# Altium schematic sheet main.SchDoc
size A4
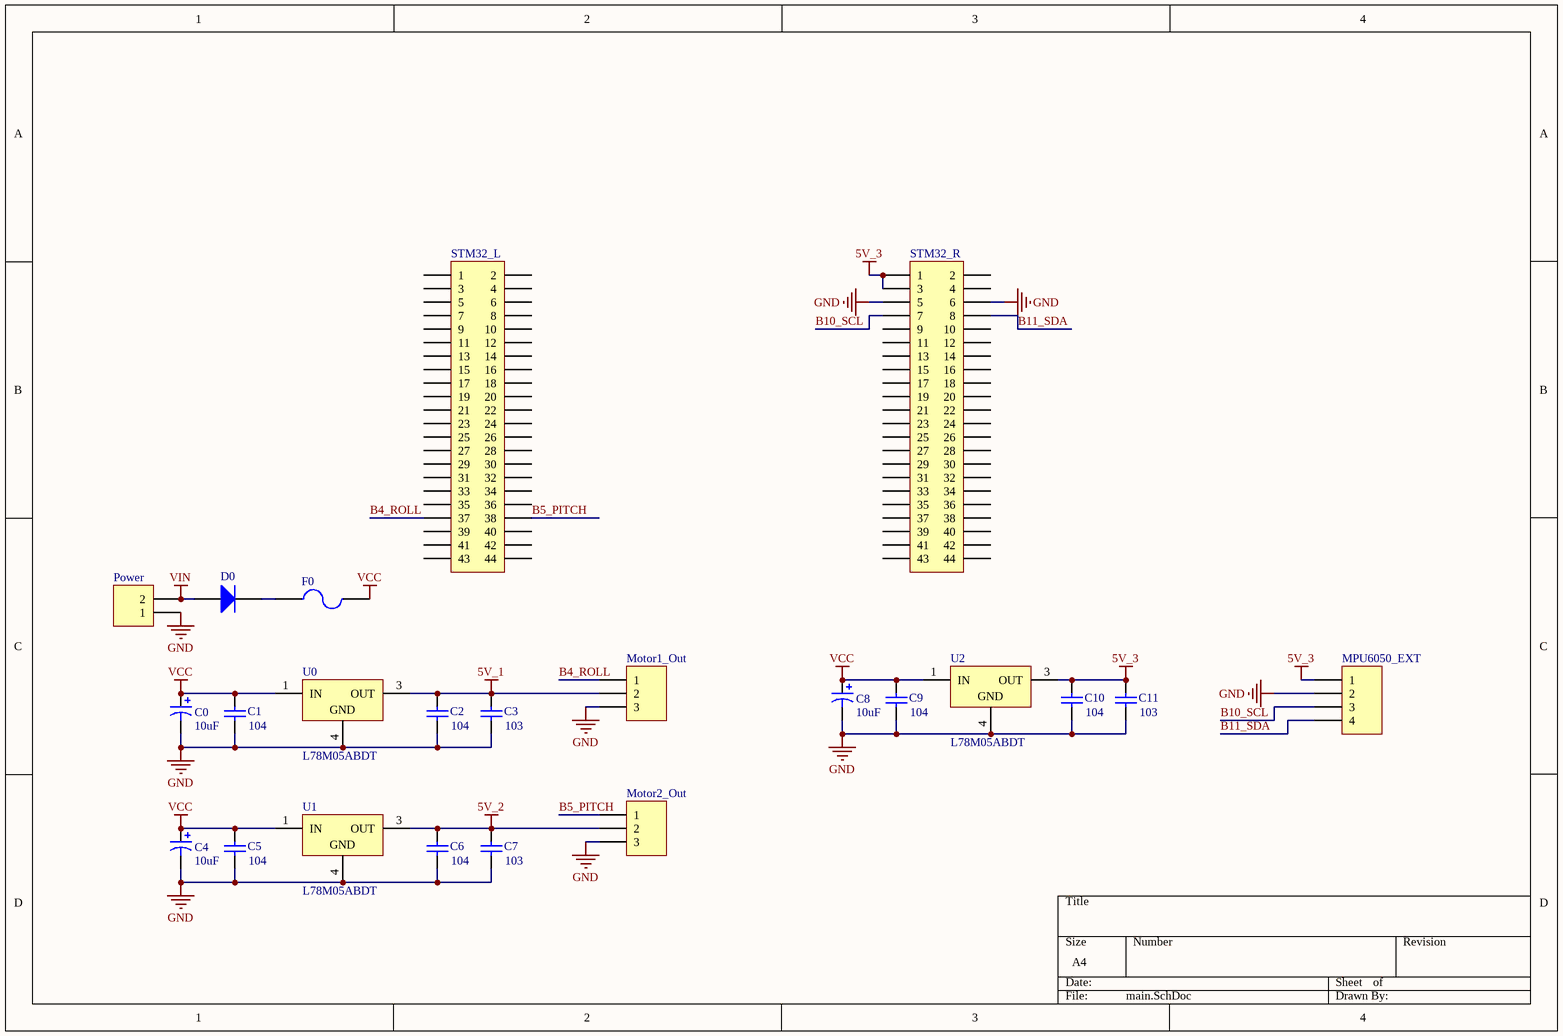
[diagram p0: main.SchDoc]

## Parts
C0  value 10uF  [1206A]  (hidden comment: Cap Pol1)
C1  value 104  [0805]  (hidden comment: Cap Semi)
C2  value 104  [0805]  (hidden comment: Cap Semi)
C3  value 103  [0805]  (hidden comment: Cap Semi)
C4  value 10uF  [1206A]  (hidden comment: Cap Pol1)
C5  value 104  [0805]  (hidden comment: Cap Semi)
C6  value 104  [0805]  (hidden comment: Cap Semi)
C7  value 103  [0805]  (hidden comment: Cap Semi)
C8  value 10uF  [1206A]  (hidden comment: Cap Pol1)
C9  value 104  [0805]  (hidden comment: Cap Semi)
C10  value 104  [0805]  (hidden comment: Cap Semi)
C11  value 103  [0805]  (hidden comment: Cap Semi)
D0  Diode  [DIODE-1206]  (value not drawn)
F0  Fuse 2  [1812]  (value not drawn)
Motor1_Out  Header 3  [HDR1X3]  (value not drawn)
Motor2_Out  Header 3  [HDR1X3]  (value not drawn)
MPU6050_EXT  Header 4  [HDR1X4]  (value not drawn)
Power  Header 2  [HDR1X2]  (value not drawn)
STM32_L  Header 22X2  [HDR2X22]  (value not drawn)
STM32_R  Header 22X2  [HDR2X22]  (value not drawn)
U0  L78M05ABDT  [TO-252]
U1  L78M05ABDT  [TO-252]
U2  L78M05ABDT  [TO-252]

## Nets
5V_1: C2.2 C3.2 Motor1_Out.2 U0.3(OUT)
5V_2: C6.2 C7.2 Motor2_Out.2 U1.3(OUT)
5V_3: C10.2 C11.2 MPU6050_EXT.1 STM32_R.1 STM32_R.3 U2.3(OUT)
GND: C0.2 C1.1 C2.1 C3.1 C4.2 C5.1 C6.1 C7.1 C8.2 C9.1 C10.1 C11.1 Motor1_Out.3 Motor2_Out.3 MPU6050_EXT.2 Power.1 STM32_R.5 STM32_R.6 U0.4(GND) U1.4(GND) U2.4(GND)
VCC: C0.1 C1.2 C4.1 C5.2 C8.1 C9.2 F0.2 U0.1(IN) U1.1(IN) U2.1(IN)
VIN: D0.1(A) Power.2
B4_ROLL: Motor1_Out.1 STM32_L.37
B5_PITCH: Motor2_Out.1 STM32_L.38
B10_SCL: MPU6050_EXT.3 STM32_R.7
B11_SDA: MPU6050_EXT.4 STM32_R.8
NetD0_2: D0.2(K) F0.1

Not connected (* = marked no-connect by the designer): STM32_L 1 2 3 4 5 6 7 8 9 10 11 12 13 14 15 16 17 18 19 20 21 22 23 24 25 26 27 28 29 30 31 32 33 34 35 36 39 40 41 42 43 44; STM32_R 2 4 9 10 11 12 13 14 15 16 17 18 19 20 21 22 23 24 25 26 27 28 29 30 31 32 33 34 35 36 37 38 39 40 41 42 43 44

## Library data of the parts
C0 C4 C8 = Cap Pol1: Polarized Capacitor (Radial)
C1-C3 C5-C7 C9-C11 = Cap Semi: Capacitor (Semiconductor SIM Model)
D0 = Diode: Default Diode
F0 = Fuse 2: Fuse
Motor1_Out Motor2_Out = Header 3: Header, 3-Pin
MPU6050_EXT = Header 4: Header, 4-Pin
Power = Header 2: Header, 2-Pin
STM32_L STM32_R = Header 22X2: Header, 22-Pin, Dual row
U0-U2 = L78M05ABDT: Precision 500mA Regulator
